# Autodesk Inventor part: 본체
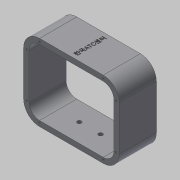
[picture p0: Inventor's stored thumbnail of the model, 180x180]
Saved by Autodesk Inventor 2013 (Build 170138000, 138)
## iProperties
Created: 2016-12
Part Number: 본체
Material: 일반
Document SubType Name: Modeling
Designer: mduedu
Density: 1 g/cm^3
Author: mduedu
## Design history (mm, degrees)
sketch "스케치1"
  geometry: L1 (-60, 72)-(60, 72); L2 (90, 42)-(90, -42); L3 (60, -72)-(-60, -72); L4 (-90, -42)-(-90, 42); A1 r 30 centre (-60, 42) between (-60, 72) and (-90, 42); A2 r 30 centre (60, 42) between (90, 42) and (60, 72); A3 r 30 centre (60, -42) between (60, -72) and (90, -42); A4 r 30 centre (-60, -42) between (-90, -42) and (-60, -72); 1 further point
  constraints: 8 end point, 8 point on circle, 8 tangent, 4 centre point, 3 equal radius, 2 parallel, 1 horizontal, 1 perpendicular
  dimensions: "d106" = 30 radius of A1; "d107" = 72 distance from line of L1 point (0, 0); "d108" = 144 distance between parallel lines of L3 L1; "d109" = 90 distance from line of L4 point (0, 0); "d110" = 180 distance between parallel lines of L2 L4
extrude "돌출1" new body sketch "스케치1" stored distance "d3" = 70; taper "d4" = 0 deg
feature "쉘1" dims "d5" = 10
sketch "스케치10"
  geometry: L1 (-30, 0)-(-30, 70) reference; 3 further points
  constraints: 2 coincident, 1 other
  dimensions: "d111" = 90 distance from line of point (60, 35) L1
feature "엠보싱1" sketch "스케치10" dims "d61" = 0.5, "d62" = 0, "d106" = 30, "d107" = 72, "d108" = 144, "d109" = 90, "d110" = 180
sketch "스케치16"
  geometry: L1 (-60, 62)-(60, 62) reference; L2 (80, 42)-(80, -42) reference; L3 (60, -62)-(-60, -62) reference; L4 (-80, -42)-(-80, 42) reference; L5 (60, 72)-(-60, 72) reference; L6 (-90, 42)-(-90, -42) reference; L7 (-60, -72)-(60, -72) reference; L8 (90, -42)-(90, 42) reference; L9 (60, 66)-(-60, 66); L10 (-84, 42)-(-84, -42); L11 (-60, -66)-(60, -66); L12 (84, -42)-(84, 42); A1 r 20 centre (60, 42) between (80, 42) and (60, 62) reference; A2 r 20 centre (60, -42) between (60, -62) and (80, -42) reference; A3 r 20 centre (-60, -42) between (-80, -42) and (-60, -62) reference; A4 r 20 centre (-60, 42) between (-60, 62) and (-80, 42) reference; A5 r 30 centre (-60, 42) between (-60, 72) and (-90, 42) reference; A6 r 30 centre (-60, -42) between (-90, -42) and (-60, -72) reference; A7 r 30 centre (60, -42) between (60, -72) and (90, -42) reference; A8 r 30 centre (60, 42) between (90, 42) and (60, 72) reference; A9 r 24 centre (-60, 42) between (-60, 66) and (-84, 42); A10 r 24 centre (-60, -42) between (-84, -42) and (-60, -66); A11 r 24 centre (60, -42) between (60, -66) and (84, -42); A12 r 24 centre (60, 42) between (84, 42) and (60, 66); 9 further points
  constraints: 8 coincident, 8 end point, 8 point on circle, 4 centre point, 7 other
  dimensions: "d124" = 6 distance between parallel lines of L9 L5
hole "구멍6" sketch "스케치16" at (-60, 66), (-84, 42), (-84, -42), (-60, -66), (60, -66), (84, -42), (84, 42), (60, 66) diameter "d113" = 3.242; stored, may be unused: countersink angle "d117" = 90 deg, drill point angle "d119" = 118 deg; dims "d114" = 7, "d115" = 4, "d116" = 2, "d118" = 9
sketch "스케치15"
  geometry: L1 (0, -70)-(0, 0) reference; L2 (-22.361, 0)-(0, 0) reference; L3 (-22.361, -70)-(-22.361, 0) reference; L4 (0, -70)-(-22.361, -70) reference; L5 (120, -70)-(0, -70) reference; L6 (120, -70)-(120, 0) reference; L7 (120, 0)-(142.361, 0) reference; L8 (142.361, 0)-(142.361, -70) reference; L9 (142.361, -70)-(120, -70) reference; L10 (0, 0)-(120, 0) reference; L11 (60, 0)-(60, -70); L12 (-22.361, -35)-(142.361, -35); C1 r 4 at (40, -35); C2 r 4 at (80, -35); 1 further point
  constraints: 4 end point, 4 midpoint, 2 centre point, 2 point on line, 1 equal radius
  dimensions: "d120" = 8 diameter of C1; "d122" = 20 distance from line of L11 C1.centre; "d123" = 40 distance of C2.centre C1.centre
extrude "돌출6" cut sketch "스케치15" stored distance "d94" = 10; taper "d95" = 0 deg
node "솔리드1"
mirror "대칭2"
node "투영된 루프5"
node "절단 모서리 투영2"
